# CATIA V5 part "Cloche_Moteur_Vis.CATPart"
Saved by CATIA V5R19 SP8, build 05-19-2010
Part number: Cloche_Moteur_Vis
Nomenclature: 70_c
Bounding box of the stored display mesh (mm): x -34.195 to 34.195, y -34.199 to 34.199, z -4 to 20.1
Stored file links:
  C:\Users\rphgr\Desktop\0_Tapis_TC520B_vitesse\Cloche_Moteur_Vis.CATPart
  C:\Users\rphgr\Desktop\0_Tapis_TC520B_vitesse\CE_Boitier_Moteur_Vis.CATProduct
  C:\Users\rphgr\Desktop\0_Tapis_TC520B_vitesse\Stator_Moteur_Vis.CATPart
  C:\Users\rphgr\Desktop\0_Tapis_TC520B_vitesse\Corps Inf de BMV.CATPart
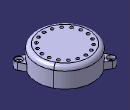
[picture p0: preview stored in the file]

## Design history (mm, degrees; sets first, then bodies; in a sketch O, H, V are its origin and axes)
Set1
  DatumSurface1 to DatumSurface4: linked copy from another document
Body1 (main body)
  AxisSystem1: origin (0, 0, 0), X (1, 0, 0), Y (0, 1, 0), Z (0, 0, 1)
  Sketch1 on ZX plane of AxisSystem1, origin (0, 0, 0), H (0, 0, 1), V (1, 0, 0)
    line L1 (-4, 32.4) -> (0, 32.4)
    line L2 (0, 32.4) -> (0, 31.5)
    line L3 (0, 31.5) -> (17.7, 31.5)
    line L4 (17.7, 31.5) -> (17.7, 14)
    line L5 (17.7, 14) -> (9.7, 14)
    line L6 (9.7, 14) -> (9.7, 11)
    line L7 (9.7, 11) -> (17.7, 11)
    point P8 (17.7, 11)
    line L8 (17.7, 11) -> (17.7, 0)
    point P9 (17.7, 0)
    line L9 (17.7, 0) -> (20.1, 0)
    line L10 (20.1, 0) -> (20.1, 34.2)
    line L11 (20.1, 34.2) -> (-4, 34.2)
    line L12 (-4, 34.2) -> (-4, 32.4)
    reference intersected line E1 (-0.9, 32.4) -> (-0.1, 32.4) from face of DatumSurface1
    reference intersected line E2 through (0, 0) direction (0, -1) from face of DatumSurface2
    distance L12 L2 = 4
    distance L1 L11 = 1.8
    distance L3 L11 = 2.7
    distance L12 L4 = 21.7
    distance L10 L12 = 24.1
    distance L7 L9 = 11
    distance L5 L9 = 14
    distance L6 L4 = 8
    horizontal: L1 H, L3 H, L5 H, L7 H, L9 H, L11 H
    vertical: L2 V, L4 V, L6 V, L8 V, L10 V, L12 V
    coincidence: P8 L4, P9 H, L1 E1, L2 E2
  Shaft1: profile Sketch1, axis Z axis, angle 360
  Fillet1: radius 5, on edge [face of Shaft1 from Sketch1.L11 | face of Shaft1 from Sketch1.L10]
  Sketch2 on face of Shaft1 from Sketch1.L12, origin (0, 0, -4), H (1, 0, 0), V (0, -1, 0)
    projected line E1 (27.1386, 31.9041) -> (19.0542, 28.4003) from edge of DatumSurface3
    projected arc E2 centre (29.0474, 27.5) radius 4.8 from (33.3405, 25.3532) to (27.1386, 31.9041) ccw from edge of DatumSurface3
    projected line E3 (29.3998, 17.4726) -> (33.3405, 25.3532) from edge of DatumSurface3
    projected arc E4 centre (0, 0) radius 34.2 from (29.3998, 17.4726) to (19.0542, 28.4003) ccw from edge of DatumSurface3
    projected circle E5 centre (29.0474, 27.5) radius 1.621 from edge of DatumSurface3
    projected line E6 (-26.6573, -31.6626) -> (-19.9244, -27.7967) from edge of DatumSurface4
    projected arc E7 centre (-29.0474, -27.5) radius 4.8 from (-33.2464, -25.1745) to (-26.6573, -31.6626) ccw from edge of DatumSurface4
    projected line E8 (-29.1815, -17.8347) -> (-33.2464, -25.1745) from edge of DatumSurface4
    projected arc E9 centre (0, 0) radius 34.2 from (-29.1815, -17.8347) to (-19.9244, -27.7967) ccw from edge of DatumSurface4
    projected circle E10 centre (-29.0474, -27.5) radius 1.621 from edge of DatumSurface4
  Pad1: profile Sketch2, direction (0, 0, 1), length 8.39
  Sketch3 on end face of Pad1, origin (-25.9295, 26.5055, 4.39), H (1, 0, 0), V (0, 1, 0)
    point P1 (-3.1179, 0.9945)
    reference projected point E1 (-3.1179, 0.9945) from axis of face of Pad1 from Sketch2.E7
    coincidence: P1 E1
  Hole1: placed by Sketch3, at (-29.0474, 27.5, 4.39) direction (0, 0, -1), diameter 4.2, through (limit type 3), counterbore diameter 8.5, counterbore depth 3.4
  Sketch4 on end face of Pad1, origin (26.8939, -24.0229, 4.39), H (1, 0, 0), V (0, 1, 0)
    point P1 (2.1534, -3.4771)
    reference projected point E1 (2.1534, -3.4771) from axis of face of Pad1 from Sketch2.E2
    coincidence: P1 E1
  Hole2: placed by Sketch4, at (29.0474, -27.5, 4.39) direction (0, 0, -1), diameter 4.2, through (limit type 3), counterbore diameter 8.5, counterbore depth 3.4
  Sketch5 on face of Shaft1 from Sketch1.L10, origin (0, 0, 20.1), H (1, 0, 0), V (0, 1, 0)
    circle A1 centre (-0.7202, 24.9896) radius 1.8
    point P1 (-0.7202, 24.9896)
    point P2 (0, 23.34)
    radius A1 = 1.8
    distance P1 O = 25
    coincidence: A1 P2, P2 V
  Pocket1: profile Sketch5, direction (0, 0, -1), through (limit type 3)
  CircPattern1: of Pocket1, instances 18, angular step 20 {= 360.0*1 deg/CircPattern1.AngularNumber}, axis from face of Shaft1 from Sketch1.L11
